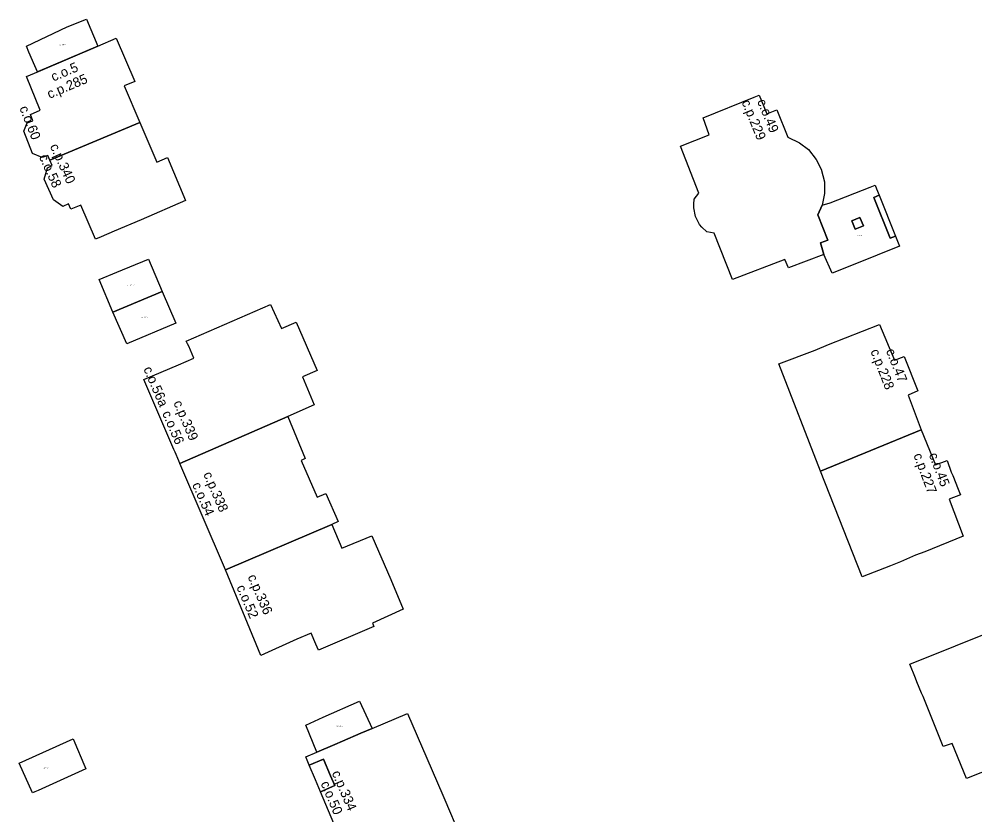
# Model space of a CAD drawing. Extents: x -600391 to -599491, y -1160176 to -1159402.
# Drawn here: x -599954.2 to -599855.3, y -1160041.6 to -1159959.3 of the extents above; entities that cross this region are included whole.
import ezdxf

# ---------------------------------------------------------------- set-up
doc = ezdxf.new("R2010")
doc.units = 0
for name, color, linetype in [('Level 10', 7, 'Continuous'), ('Level 12', 7, 'Continuous'), ('Level 24', 7, 'Continuous'), ('Level 25', 7, 'Continuous'), ('Level 61', 7, 'Continuous'), ('Level 62', 7, 'Continuous')]:
    doc.layers.add(name, color=color, linetype=linetype)

msp = doc.modelspace()

# ---------------------------------------------------------------- linework, layer by layer
at = {"layer": 'Level 61'}
for points in [[(-599949.22, -1159960.09), (-599947.24, -1159959.3)], [(-599947.24, -1159959.3), (-599946.05, -1159962.1)], [(-599953.46, -1159962.09), (-599949.22, -1159960.09)], [(-599946.05, -1159962.1), (-599944.17, -1159961.26)], [(-599944.17, -1159961.26), (-599942.23, -1159965.74)], [(-599953.19, -1159962.73), (-599953.46, -1159962.09)], [(-599946.05, -1159962.1), (-599952.31, -1159964.76)], [(-599952.19, -1159964.71), (-599946.05, -1159962.1)], [(-599952.58, -1159964.14), (-599953.19, -1159962.73)], [(-599952.31, -1159964.76), (-599952.58, -1159964.14)], [(-599953.45, -1159965.24), (-599952.19, -1159964.71)], [(-599952.03, -1159968.71), (-599953.45, -1159965.24)], [(-599942.23, -1159965.74), (-599943.32, -1159966.19)], [(-599943.32, -1159966.19), (-599941.71, -1159969.98)], [(-599878.09, -1159967.39), (-599877.6, -1159967.16)], [(-599877.6, -1159967.16), (-599876.78, -1159969.1)], [(-599883.4, -1159969.52), (-599878.09, -1159967.39)], [(-599953.02, -1159969.15), (-599952.03, -1159968.71)], [(-599952.79, -1159969.82), (-599953.02, -1159969.15)], [(-599876.78, -1159969.1), (-599875.77, -1159968.7)], [(-599875.77, -1159968.7), (-599874.62, -1159971.5)], [(-599953.73, -1159970.9), (-599953.37, -1159970.02)], [(-599953.37, -1159970.02), (-599952.79, -1159969.82)], [(-599951.02, -1159973.89), (-599941.71, -1159969.98)], [(-599941.71, -1159969.98), (-599951.02, -1159973.89)], [(-599941.71, -1159969.98), (-599939.96, -1159974.11)], [(-599882.77, -1159971.27), (-599883.4, -1159969.52)], [(-599952.82, -1159973.21), (-599953.73, -1159970.9)], [(-599885.73, -1159972.46), (-599882.77, -1159971.27)], [(-599874.62, -1159971.5), (-599873.43, -1159972.09)], [(-599873.43, -1159972.09), (-599872.49, -1159972.79)], [(-599951.83, -1159973.61), (-599952.82, -1159973.21)], [(-599883.85, -1159977.31), (-599885.73, -1159972.46)], [(-599872.49, -1159972.79), (-599871.68, -1159973.81)], [(-599951.22, -1159973.4), (-599951.83, -1159973.61)], [(-599951.02, -1159973.89), (-599951.22, -1159973.4)], [(-599950.78, -1159974.44), (-599951.02, -1159973.89)], [(-599939.96, -1159974.11), (-599938.85, -1159973.63)], [(-599938.85, -1159973.63), (-599936.99, -1159978.05)], [(-599871.68, -1159973.81), (-599871.16, -1159974.81)], [(-599951.62, -1159975.86), (-599951.26, -1159974.68)], [(-599951.26, -1159974.68), (-599950.78, -1159974.44)], [(-599871.16, -1159974.81), (-599870.83, -1159976.12)], [(-599950.65, -1159978), (-599951.62, -1159975.86)], [(-599870.83, -1159976.12), (-599870.82, -1159977.34)], [(-599870.25, -1159978.31), (-599866.08, -1159976.68)], [(-599866.08, -1159976.68), (-599865.59, -1159976.49)], [(-599865.59, -1159976.49), (-599865.45, -1159976.85)], [(-599865.45, -1159976.85), (-599865.18, -1159977.52)], [(-599949.7, -1159978.67), (-599950.65, -1159978)], [(-599936.99, -1159978.05), (-599941.56, -1159980.07)], [(-599884.35, -1159978.45), (-599884.33, -1159977.92)], [(-599884.33, -1159977.92), (-599883.85, -1159977.31)], [(-599870.82, -1159977.34), (-599871.08, -1159978.56)], [(-599865.18, -1159977.52), (-599865.73, -1159977.74)], [(-599865.73, -1159977.74), (-599865.18, -1159977.52)], [(-599865.73, -1159977.74), (-599864.03, -1159981.96)], [(-599864.03, -1159981.96), (-599865.73, -1159977.74)], [(-599865.18, -1159977.52), (-599863.47, -1159981.74)], [(-599949.1, -1159978.41), (-599949.7, -1159978.67)], [(-599948.84, -1159978.97), (-599949.1, -1159978.41)], [(-599947.83, -1159978.53), (-599948.84, -1159978.97)], [(-599946.31, -1159982.06), (-599947.83, -1159978.53)], [(-599884.36, -1159978.82), (-599884.35, -1159978.45)], [(-599884.19, -1159979.72), (-599884.36, -1159978.82)], [(-599871.5, -1159979.53), (-599871.08, -1159978.56)], [(-599871.08, -1159978.56), (-599871.5, -1159979.53)], [(-599871.08, -1159978.56), (-599870.25, -1159978.31)], [(-599941.56, -1159980.07), (-599944.37, -1159981.25)], [(-599883.78, -1159980.55), (-599884.19, -1159979.72)], [(-599870.47, -1159982.16), (-599871.5, -1159979.53)], [(-599871.5, -1159979.53), (-599870.47, -1159982.16)], [(-599868.01, -1159980.16), (-599867.16, -1159979.83)], [(-599867.16, -1159979.83), (-599868.01, -1159980.16)], [(-599867.65, -1159981.02), (-599868.01, -1159980.16)], [(-599868.01, -1159980.16), (-599867.65, -1159981.02)], [(-599867.16, -1159979.83), (-599866.8, -1159980.67)], [(-599866.8, -1159980.67), (-599867.16, -1159979.83)], [(-599883.52, -1159980.81), (-599883.78, -1159980.55)], [(-599883.02, -1159981.3), (-599883.52, -1159980.81)], [(-599866.8, -1159980.67), (-599867.65, -1159981.02)], [(-599867.65, -1159981.02), (-599866.8, -1159980.67)], [(-599945.7, -1159981.82), (-599946.31, -1159982.06)], [(-599944.37, -1159981.25), (-599945.7, -1159981.82)], [(-599882.25, -1159981.43), (-599883.02, -1159981.3)], [(-599880.35, -1159986.25), (-599882.25, -1159981.43)], [(-599871.24, -1159982.46), (-599870.47, -1159982.16)], [(-599870.47, -1159982.16), (-599871.24, -1159982.46)], [(-599864.03, -1159981.96), (-599863.47, -1159981.74)], [(-599863.47, -1159981.74), (-599864.03, -1159981.96)], [(-599863.47, -1159981.74), (-599863.05, -1159982.79)], [(-599870.9, -1159983.65), (-599871.24, -1159982.46)], [(-599871.24, -1159982.46), (-599870.9, -1159983.65)], [(-599863.05, -1159982.79), (-599867.69, -1159984.66)], [(-599944.09, -1159985.47), (-599940.81, -1159984.12)], [(-599940.81, -1159984.12), (-599939.4, -1159987.48)], [(-599870.9, -1159983.65), (-599874.54, -1159985.04)], [(-599870.03, -1159985.57), (-599870.9, -1159983.65)], [(-599874.92, -1159984.16), (-599880.35, -1159986.25)], [(-599874.54, -1159985.04), (-599874.92, -1159984.16)], [(-599867.69, -1159984.66), (-599870.03, -1159985.57)], [(-599945.92, -1159986.25), (-599944.09, -1159985.47)], [(-599944.49, -1159989.63), (-599945.92, -1159986.25)], [(-599939.4, -1159987.48), (-599944.49, -1159989.63)], [(-599944.49, -1159989.63), (-599939.4, -1159987.48)], [(-599939.4, -1159987.48), (-599937.99, -1159990.76)], [(-599936.93, -1159992.6), (-599928.17, -1159988.84)], [(-599928.17, -1159988.84), (-599927.05, -1159991.32)], [(-599943.06, -1159992.88), (-599944.49, -1159989.63)], [(-599937.99, -1159990.76), (-599943.06, -1159992.88)], [(-599927.05, -1159991.32), (-599925.53, -1159990.66)], [(-599925.53, -1159990.66), (-599923.34, -1159995.66)], [(-599870.42, -1159992.96), (-599865.14, -1159990.91)], [(-599865.14, -1159990.91), (-599863.59, -1159994.57)], [(-599936.78, -1159992.88), (-599936.93, -1159992.6)], [(-599936.65, -1159993.15), (-599936.78, -1159992.88)], [(-599871.79, -1159993.55), (-599870.42, -1159992.96)], [(-599936.11, -1159994.38), (-599936.65, -1159993.15)], [(-599875.57, -1159994.97), (-599871.79, -1159993.55)], [(-599937.7, -1159995.08), (-599936.11, -1159994.38)], [(-599871.25, -1160006.08), (-599875.57, -1159994.97)], [(-599863.59, -1159994.57), (-599862.57, -1159994.21)], [(-599862.57, -1159994.21), (-599861.17, -1159997.75)], [(-599941.31, -1159996.57), (-599937.7, -1159995.08)], [(-599923.34, -1159995.66), (-599924.86, -1159996.29)], [(-599938.19, -1160003.83), (-599941.31, -1159996.57)], [(-599924.86, -1159996.29), (-599923.66, -1159999.22)], [(-599861.17, -1159997.75), (-599862.15, -1159998.22)], [(-599862.15, -1159998.22), (-599860.81, -1160001.78)], [(-599923.66, -1159999.22), (-599926.39, -1160000.41)], [(-599926.39, -1160000.41), (-599937.57, -1160005.27)], [(-599937.57, -1160005.27), (-599926.39, -1160000.41)], [(-599926.39, -1160000.41), (-599924.61, -1160004.77)], [(-599871.25, -1160006.08), (-599860.81, -1160001.78)], [(-599860.81, -1160001.78), (-599871.25, -1160006.08)], [(-599860.81, -1160001.78), (-599859.34, -1160005.42)], [(-599938.07, -1160004.1), (-599938.19, -1160003.83)], [(-599937.69, -1160004.99), (-599938.07, -1160004.1)], [(-599924.61, -1160004.77), (-599925.01, -1160004.95)], [(-599937.57, -1160005.27), (-599937.69, -1160004.99)], [(-599932.85, -1160016.29), (-599937.57, -1160005.27)], [(-599925.01, -1160004.95), (-599923.35, -1160008.77)], [(-599859.34, -1160005.42), (-599858.14, -1160004.98)], [(-599858.14, -1160004.98), (-599857.7, -1160006.16)], [(-599866.94, -1160017.01), (-599871.25, -1160006.08)], [(-599857.7, -1160006.16), (-599857.55, -1160006.52)], [(-599857.55, -1160006.52), (-599857, -1160007.94)], [(-599923.35, -1160008.77), (-599922.44, -1160008.37)], [(-599922.44, -1160008.37), (-599921.18, -1160011.29)], [(-599856.75, -1160008.52), (-599857.93, -1160008.98)], [(-599857, -1160007.94), (-599856.84, -1160008.28)], [(-599856.84, -1160008.28), (-599856.75, -1160008.52)], [(-599857.93, -1160008.98), (-599856.48, -1160012.78)], [(-599932.85, -1160016.29), (-599921.82, -1160011.57)], [(-599921.82, -1160011.57), (-599932.85, -1160016.29)], [(-599921.18, -1160011.29), (-599921.82, -1160011.57)], [(-599921.82, -1160011.57), (-599920.79, -1160014.05)], [(-599920.79, -1160014.05), (-599917.69, -1160012.75)], [(-599917.69, -1160012.75), (-599915.74, -1160017.28)], [(-599856.48, -1160012.78), (-599860.44, -1160014.4)], [(-599861.42, -1160014.77), (-599862.97, -1160015.44)], [(-599860.44, -1160014.4), (-599861.42, -1160014.77)], [(-599862.97, -1160015.44), (-599863.99, -1160015.86)], [(-599929.18, -1160025.13), (-599932.85, -1160016.29)], [(-599863.99, -1160015.86), (-599866.94, -1160017.01)], [(-599915.74, -1160017.28), (-599914.45, -1160020.33)], [(-599914.45, -1160020.33), (-599917.63, -1160021.78)], [(-599917.47, -1160022.13), (-599923.2, -1160024.57)], [(-599917.63, -1160021.78), (-599917.47, -1160022.13)], [(-599862, -1160026.02), (-599852.53, -1160022.25)], [(-599925.46, -1160023.46), (-599929.18, -1160025.13)], [(-599923.98, -1160022.82), (-599925.46, -1160023.46)], [(-599923.48, -1160023.97), (-599923.98, -1160022.82)], [(-599923.34, -1160024.26), (-599923.48, -1160023.97)], [(-599923.2, -1160024.57), (-599923.34, -1160024.26)], [(-599861.42, -1160027.49), (-599862, -1160026.02)], [(-599861.26, -1160027.85), (-599861.42, -1160027.49)], [(-599860.77, -1160029.04), (-599861.26, -1160027.85)], [(-599860.61, -1160029.37), (-599860.77, -1160029.04)], [(-599858.54, -1160034.55), (-599860.61, -1160029.37)], [(-599922.73, -1160031.529), (-599918.98, -1160029.87)], [(-599918.98, -1160029.87), (-599917.67, -1160032.68)], [(-599924.54, -1160032.33), (-599922.73, -1160031.529)], [(-599917.67, -1160032.68), (-599914.01, -1160031.15)], [(-599914.01, -1160031.15), (-599912.01, -1160035.75)], [(-599923.39, -1160035.13), (-599924.54, -1160032.33)], [(-599918.82, -1160033.16), (-599920.74, -1160033.99)], [(-599920.74, -1160033.99), (-599918.82, -1160033.16)], [(-599917.67, -1160032.68), (-599918.82, -1160033.16)], [(-599918.82, -1160033.16), (-599917.67, -1160032.68)], [(-599954.21, -1160036.28), (-599948.61, -1160033.75)], [(-599948.61, -1160033.75), (-599948.43, -1160034.17)], [(-599948.43, -1160034.17), (-599947.51, -1160036.38)], [(-599921.53, -1160034.33), (-599923.39, -1160035.13)], [(-599923.39, -1160035.13), (-599921.53, -1160034.33)], [(-599920.74, -1160033.99), (-599921.53, -1160034.33)], [(-599921.53, -1160034.33), (-599920.74, -1160033.99)], [(-599857.6, -1160034.25), (-599858.54, -1160034.55)], [(-599856.12, -1160037.87), (-599857.6, -1160034.25)], [(-599924.54, -1160035.63), (-599923.39, -1160035.13)], [(-599952.82, -1160039.34), (-599954.21, -1160036.28)], [(-599947.51, -1160036.38), (-599947.31, -1160036.86)], [(-599924.18, -1160036.48), (-599924.54, -1160035.63)], [(-599924.18, -1160036.48), (-599922.7, -1160035.85)], [(-599922.7, -1160035.85), (-599924.18, -1160036.48)], [(-599923.53, -1160038.01), (-599924.18, -1160036.48)], [(-599922.7, -1160035.85), (-599921.96, -1160037.59)], [(-599921.96, -1160037.59), (-599922.7, -1160035.85)], [(-599912.01, -1160035.75), (-599910.34, -1160039.6)], [(-599947.31, -1160036.86), (-599952.25, -1160039.09)], [(-599921.96, -1160037.59), (-599921.53, -1160038.6)], [(-599921.53, -1160038.6), (-599921.96, -1160037.59)], [(-599854.64, -1160037.29), (-599856.12, -1160037.87)], [(-599923.02, -1160039.23), (-599923.53, -1160038.01)], [(-599952.58, -1160039.23), (-599952.82, -1160039.34)], [(-599952.25, -1160039.09), (-599952.58, -1160039.23)], [(-599921.53, -1160038.6), (-599923.02, -1160039.23)], [(-599923.02, -1160039.23), (-599921.53, -1160038.6)], [(-599919.51, -1160047.51), (-599923.02, -1160039.23)], [(-599910.34, -1160039.6), (-599909.43, -1160041.69)]]:
    msp.add_lwpolyline(points, dxfattribs=at)
at = {"layer": 'Level 62'}
for points in [[(-599953.46, -1159962.09), (-599949.22, -1159960.09), (-599947.24, -1159959.3), (-599946.05, -1159962.1), (-599952.31, -1159964.76), (-599952.58, -1159964.14), (-599953.19, -1159962.73), (-599953.46, -1159962.09)], [(-599941.71, -1159969.98), (-599951.02, -1159973.89), (-599951.22, -1159973.4), (-599951.83, -1159973.61), (-599952.82, -1159973.21), (-599953.73, -1159970.9), (-599953.37, -1159970.02), (-599952.79, -1159969.82), (-599953.02, -1159969.15), (-599952.03, -1159968.71), (-599953.45, -1159965.24), (-599952.19, -1159964.71), (-599946.05, -1159962.1), (-599944.17, -1159961.26), (-599942.23, -1159965.74), (-599943.32, -1159966.19), (-599941.71, -1159969.98)], [(-599883.52, -1159980.81), (-599883.78, -1159980.55), (-599884.19, -1159979.72), (-599884.36, -1159978.82), (-599884.35, -1159978.45), (-599884.33, -1159977.92), (-599883.85, -1159977.31), (-599885.73, -1159972.46), (-599882.77, -1159971.27), (-599883.4, -1159969.52), (-599878.09, -1159967.39), (-599877.6, -1159967.16), (-599876.78, -1159969.1), (-599875.77, -1159968.7), (-599874.62, -1159971.5), (-599873.43, -1159972.09), (-599872.49, -1159972.79), (-599871.68, -1159973.81), (-599871.16, -1159974.81), (-599870.83, -1159976.12), (-599870.82, -1159977.34), (-599871.08, -1159978.56), (-599871.5, -1159979.53), (-599870.47, -1159982.16), (-599871.24, -1159982.46), (-599870.9, -1159983.65), (-599874.54, -1159985.04), (-599874.92, -1159984.16), (-599880.35, -1159986.25), (-599882.25, -1159981.43), (-599883.02, -1159981.3), (-599883.52, -1159980.81)], [(-599941.56, -1159980.07), (-599944.37, -1159981.25), (-599945.7, -1159981.82), (-599946.31, -1159982.06), (-599947.83, -1159978.53), (-599948.84, -1159978.97), (-599949.1, -1159978.41), (-599949.7, -1159978.67), (-599950.65, -1159978), (-599951.62, -1159975.86), (-599951.26, -1159974.68), (-599950.78, -1159974.44), (-599951.02, -1159973.89), (-599941.71, -1159969.98), (-599939.96, -1159974.11), (-599938.85, -1159973.63), (-599936.99, -1159978.05), (-599941.56, -1159980.07)], [(-599870.9, -1159983.65), (-599871.24, -1159982.46), (-599870.47, -1159982.16), (-599871.5, -1159979.53), (-599871.08, -1159978.56), (-599870.25, -1159978.31), (-599866.08, -1159976.68), (-599865.59, -1159976.49), (-599865.45, -1159976.85), (-599865.18, -1159977.52), (-599865.73, -1159977.74), (-599864.03, -1159981.96), (-599863.47, -1159981.74), (-599863.05, -1159982.79), (-599867.69, -1159984.66), (-599870.03, -1159985.57), (-599870.9, -1159983.65)], [(-599865.18, -1159977.52), (-599863.47, -1159981.74), (-599864.03, -1159981.96), (-599865.73, -1159977.74), (-599865.18, -1159977.52)], [(-599866.8, -1159980.67), (-599867.65, -1159981.02), (-599868.01, -1159980.16), (-599867.16, -1159979.83), (-599866.8, -1159980.67)], [(-599867.16, -1159979.83), (-599868.01, -1159980.16), (-599867.65, -1159981.02), (-599866.8, -1159980.67), (-599867.16, -1159979.83)], [(-599944.09, -1159985.47), (-599940.81, -1159984.12), (-599939.4, -1159987.48), (-599944.49, -1159989.63), (-599945.92, -1159986.25), (-599944.09, -1159985.47)], [(-599944.49, -1159989.63), (-599939.4, -1159987.48), (-599937.99, -1159990.76), (-599943.06, -1159992.88), (-599944.49, -1159989.63)], [(-599936.78, -1159992.88), (-599936.93, -1159992.6), (-599928.17, -1159988.84), (-599927.05, -1159991.32), (-599925.53, -1159990.66), (-599923.34, -1159995.66), (-599924.86, -1159996.29), (-599923.66, -1159999.22), (-599926.39, -1160000.41), (-599937.57, -1160005.27), (-599937.69, -1160004.99), (-599938.07, -1160004.1), (-599938.19, -1160003.83), (-599941.31, -1159996.57), (-599937.7, -1159995.08), (-599936.11, -1159994.38), (-599936.65, -1159993.15), (-599936.78, -1159992.88)], [(-599871.79, -1159993.55), (-599870.42, -1159992.96), (-599865.14, -1159990.91), (-599863.59, -1159994.57), (-599862.57, -1159994.21), (-599861.17, -1159997.75), (-599862.15, -1159998.22), (-599860.81, -1160001.78), (-599871.25, -1160006.08), (-599875.57, -1159994.97), (-599871.79, -1159993.55)], [(-599921.18, -1160011.29), (-599921.82, -1160011.57), (-599932.85, -1160016.29), (-599937.57, -1160005.27), (-599926.39, -1160000.41), (-599924.61, -1160004.77), (-599925.01, -1160004.95), (-599923.35, -1160008.77), (-599922.44, -1160008.37), (-599921.18, -1160011.29)], [(-599857.7, -1160006.16), (-599857.55, -1160006.52), (-599857, -1160007.94), (-599856.84, -1160008.28), (-599856.75, -1160008.52), (-599857.93, -1160008.98), (-599856.48, -1160012.78), (-599860.44, -1160014.4), (-599861.42, -1160014.77), (-599862.97, -1160015.44), (-599863.99, -1160015.86), (-599866.94, -1160017.01), (-599871.25, -1160006.08), (-599860.81, -1160001.78), (-599859.34, -1160005.42), (-599858.14, -1160004.98), (-599857.7, -1160006.16)], [(-599923.2, -1160024.57), (-599923.34, -1160024.26), (-599923.48, -1160023.97), (-599923.98, -1160022.82), (-599925.46, -1160023.46), (-599929.18, -1160025.13), (-599932.85, -1160016.29), (-599921.82, -1160011.57), (-599920.79, -1160014.05), (-599917.69, -1160012.75), (-599915.74, -1160017.28), (-599914.45, -1160020.33), (-599917.63, -1160021.78), (-599917.47, -1160022.13), (-599923.2, -1160024.57)], [(-599852.41, -1160036.41), (-599852.87, -1160036.6), (-599854.22, -1160037.14), (-599854.64, -1160037.29), (-599856.12, -1160037.87), (-599857.6, -1160034.25), (-599858.54, -1160034.55), (-599860.61, -1160029.37), (-599860.77, -1160029.04), (-599861.26, -1160027.85), (-599861.42, -1160027.49), (-599862, -1160026.02), (-599852.53, -1160022.25), (-599847.55, -1160034.39), (-599852.41, -1160036.41)], [(-599917.67, -1160032.68), (-599918.82, -1160033.16), (-599920.74, -1160033.99), (-599921.53, -1160034.33), (-599923.39, -1160035.13), (-599924.54, -1160032.33), (-599922.73, -1160031.529), (-599918.98, -1160029.87), (-599917.67, -1160032.68)], [(-599917.67, -1160032.68), (-599914.01, -1160031.15), (-599912.01, -1160035.75), (-599910.34, -1160039.6), (-599909.43, -1160041.69), (-599908.93, -1160042.93), (-599919.51, -1160047.51), (-599923.02, -1160039.23), (-599921.53, -1160038.6), (-599921.96, -1160037.59), (-599922.7, -1160035.85), (-599924.18, -1160036.48), (-599924.54, -1160035.63), (-599923.39, -1160035.13), (-599921.53, -1160034.33), (-599920.74, -1160033.99), (-599918.82, -1160033.16), (-599917.67, -1160032.68)], [(-599952.58, -1160039.23), (-599952.82, -1160039.34), (-599954.21, -1160036.28), (-599948.61, -1160033.75), (-599948.43, -1160034.17), (-599947.51, -1160036.38), (-599947.31, -1160036.86), (-599952.25, -1160039.09), (-599952.58, -1160039.23)], [(-599923.02, -1160039.23), (-599923.53, -1160038.01), (-599924.18, -1160036.48), (-599922.7, -1160035.85), (-599921.96, -1160037.59), (-599921.53, -1160038.6), (-599923.02, -1160039.23)]]:
    msp.add_lwpolyline(points, dxfattribs=at)

# ---------------------------------------------------------------- texts
at = {"layer": 'Level 10'}
for s, rotation, p in [('c.o.5', 23.02931, (-599950.657, -1159965.77)), ('c.o.49', 292.32809, (-599877.824, -1159967.797)), ('c.o.60', 291.5003, (-599954.201, -1159968.494)), ('c.o.58', 294.38136, (-599952.185, -1159973.544)), ('c.o.47', 291.49287, (-599864.483, -1159993.607)), ('c.o.56a', 293.19107, (-599941.366, -1159995.483)), ('c.o.56', 293.19107, (-599939.422, -1160000.063)), ('c.o.45', 290.64054, (-599860.038, -1160004.365)), ('c.o.54', 293.36035, (-599936.315, -1160007.458)), ('c.o.52', 293.27834, (-599931.73, -1160018.076)), ('c.o.50', 293.17301, (-599923.017, -1160038.369))]:
    msp.add_text(s, height=1, rotation=rotation, dxfattribs=at).set_placement(p)
at = {"layer": 'Level 12'}
for s, rotation, p in [('c.p.285', 23.02931, (-599951.059, -1159967.558)), ('c.p.229', 292.32809, (-599879.429, -1159967.871)), ('c.p.340', 294.38136, (-599951.046, -1159972.448)), ('c.p.228', 291.49287, (-599866.091, -1159993.652)), ('c.p.339', 293.19107, (-599938.258, -1159998.986)), ('c.p.227', 290.64054, (-599861.638, -1160004.407)), ('c.p.338', 293.36035, (-599935.162, -1160006.373)), ('c.p.336', 293.27834, (-599930.57, -1160016.987)), ('c.p.334', 293.17301, (-599921.86, -1160037.283))]:
    msp.add_text(s, height=1, rotation=rotation, dxfattribs=at).set_placement(p)
at = {"layer": 'Level 24'}
msp.add_text('c.z.193', height=0.1, dxfattribs=at).set_placement((-599867.419, -1159981.737))
at = {"layer": 'Level 25'}
for s, p in [('c.pp.285_A', (-599950.043, -1159962.017)), ('c.pp.340_A', (-599942.963, -1159986.877)), ('c.pp.339_A', (-599941.553, -1159990.197)), ('c.pp.334_A', (-599921.413, -1160032.487)), ('c.pp.333_A', (-599951.863, -1160036.807))]:
    msp.add_text(s, height=0.1, dxfattribs=at).set_placement(p)

doc.saveas('drawing.dxf')
